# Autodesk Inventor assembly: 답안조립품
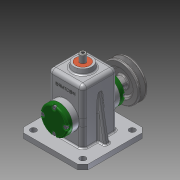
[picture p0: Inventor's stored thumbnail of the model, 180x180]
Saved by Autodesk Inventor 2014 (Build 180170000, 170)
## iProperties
Created: 2016-02
Part Number: 답안조립품
Document SubType Name: Assembly
Designer: 703-04
Author: 703-04
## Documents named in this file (16)
- C:\Users\703-04\Desktop\460212V1010[1]\답안조립품.iam
- C:\Users\703-04\Desktop\460212V1010[1]\1-본체.ipt
- C:\Users\703-04\Desktop\460212V1010[1]\V벨트풀리.ipt
- C:\Users\703-04\Desktop\460212V1010[1]\고정핀 1.2 x 10.ipt
- C:\Users\703-04\Desktop\460212V1010[1]\뒤커버.ipt
- C:\Users\703-04\Desktop\460212V1010[1]\링크.ipt
- C:\Users\703-04\Desktop\460212V1010[1]\멈춤나사 M3x8.ipt
- C:\Users\703-04\Desktop\460212V1010[1]\베어링 12 x 32 x 10.ipt
- C:\Users\703-04\Desktop\460212V1010[1]\볼트 M4 x 12.ipt
- C:\Users\703-04\Desktop\460212V1010[1]\부시.ipt
- C:\Users\703-04\Desktop\460212V1010[1]\슬라이드.ipt
- C:\Users\703-04\Desktop\460212V1010[1]\앞커버.ipt
- C:\Users\703-04\Desktop\460212V1010[1]\오일실 12 25 7.ipt
- C:\Users\703-04\Desktop\460212V1010[1]\키 4 x 4 x 10.ipt
- C:\Users\703-04\Desktop\460212V1010[1]\편심축.ipt
- C:\Users\703-04\Desktop\460212V1010[1]\핀 5 x 18.ipt
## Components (12 placed, 5 different names)
1. 1-본체:1
2. V벨트풀리:1 — 각도:2
3. 고정핀 1.2 x 10:1 — 플러쉬:2
4. 핀 5 x 18:1 — 플러쉬:1
5. ISO 4762 M4 x 12:2
6. ISO 4762 M4 x 12:3
7. ISO 4762 M4 x 12:4
8. ISO 4762 M4 x 12:5
9. ISO 4762 M4 x 12:1
10. ISO 4762 M4 x 12:6
11. ISO 4762 M4 x 12:7
12. ISO 4762 M4 x 12:8
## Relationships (3: Flush 2, Angle 1)
- 각도:2 [Angle]: V벨트풀리:1
- 플러쉬:1 [Flush]: 핀 5 x 18:1
- 플러쉬:2 [Flush]: 고정핀 1.2 x 10:1
